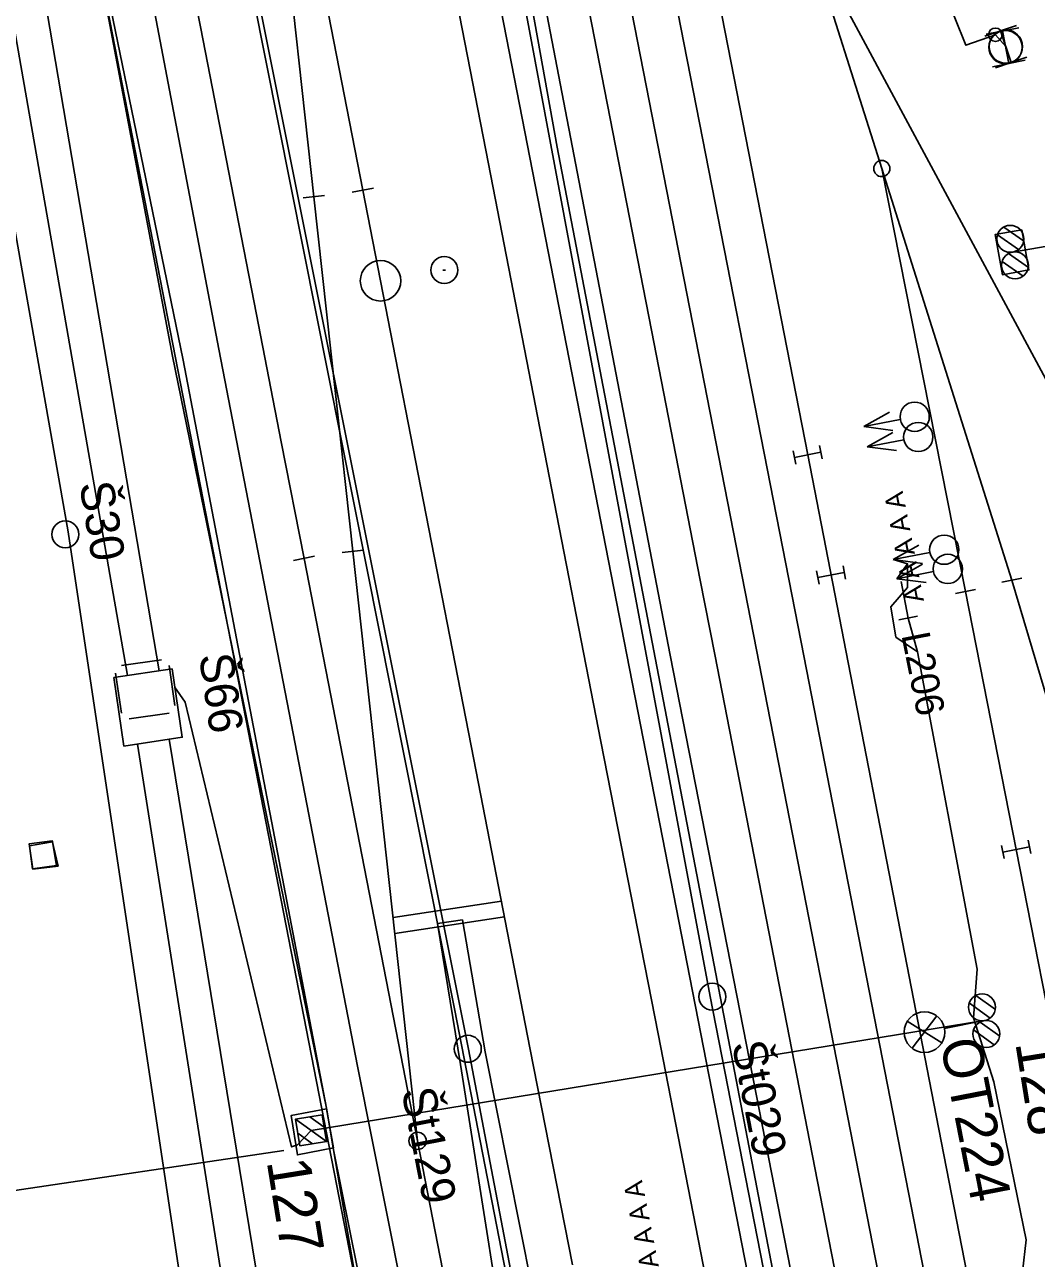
# Model space of a CAD drawing. Extents: x -545846 to -545044, y -1122650 to -1119108.
# Drawn here: x -545638.75 to -545601.28, y -1119708.74 to -1119663.02 of the extents above; entities that cross this region are included whole.
import ezdxf

# ---------------------------------------------------------------- set-up
doc = ezdxf.new("R2010")
doc.units = 0
for name, color, linetype in [('osvětlené plochy-hodnota-obrys', 7, 'Continuous'), ('Vrstva 1', 7, 'Continuous'), ('Vrstva 1 - Koleje', 7, 'Continuous'), ('Vrstva 11 - Trakce', 7, 'Continuous'), ('Vrstva 12', 7, 'Continuous'), ('Vrstva 12 - Trakce zaklady', 7, 'Continuous'), ('Vrstva 19 - Staniceni', 7, 'Continuous'), ('Vrstva 2', 7, 'Continuous'), ('Vrstva 2 - Vyhybky', 7, 'Continuous'), ('Vrstva 25', 7, 'Continuous'), ('Vrstva 26', 7, 'Continuous'), ('Vrstva 27', 7, 'Continuous'), ('Vrstva 28 - zabzar', 7, 'Continuous'), ('Vrstva 3', 7, 'Continuous'), ('Vrstva 3 - Lisy - Pocitaci body', 7, 'Continuous'), ('Vrstva 34', 7, 'Continuous'), ('Vrstva 35', 7, 'Continuous'), ('Vrstva 36', 7, 'Continuous'), ('Vrstva 4 - Teren - stezky - prechody - plochy', 7, 'Continuous'), ('Vrstva 43', 7, 'Continuous'), ('Vrstva 44', 7, 'Continuous'), ('Vrstva 6 - Navesti', 7, 'Continuous'), ('Vrstva 63', 7, 'Continuous'), ('Vrstva 7 - Namezniky-vystroj', 7, 'Continuous')]:
    doc.layers.add(name, color=color, linetype=linetype)

msp = doc.modelspace()

# ---------------------------------------------------------------- linework, layer by layer
at = {"layer": 'osvětlené plochy-hodnota-obrys'}
for points in [[(-545716.386, -1119223.717), (-545705.994, -1119221.66), (-545669.439, -1119408.759), (-545659.4, -1119462.635), (-545647.69, -1119521.347), (-545640.519, -1119558.729), (-545633.585, -1119589.698), (-545629.517, -1119613.814), (-545623.042, -1119645.057), (-545619.034, -1119667.556), (-545607.519, -1119727.517)], [(-545610.895, -1119760.665), (-545622.836, -1119699.488), (-545637.26, -1119626.872), (-545653.542, -1119543.449), (-545716.386, -1119223.717)], [(-545618.794, -1119749.17), (-545664.282, -1119515.639)], [(-545577.736, -1119667.874), (-545599.026, -1119679.685), (-545626.403, -1119628.801)]]:
    msp.add_lwpolyline(points, dxfattribs=at)
at = {"layer": 'Vrstva 1'}
for p, q in [((-545607.007, -1119668.348), (-545603.908, -1119684.024)), ((-545602.189, -1119683.602), (-545597.779, -1119698.482)), ((-545603.908, -1119684.024), (-545602.029, -1119693.583))]:
    msp.add_line(p, q, dxfattribs=at)
for points in [[(-545616.651, -1119643.635), (-545609.752, -1119678.959), (-545604.997, -1119703.439)], [(-545610.067, -1119658.662), (-545609.834, -1119659.409), (-545607.007, -1119668.348), (-545602.189, -1119683.602)], [(-545602.029, -1119693.583), (-545598.565, -1119711.307), (-545594.583, -1119731.822), (-545589.431, -1119758.323), (-545585.705, -1119777.481), (-545581.931, -1119796.878), (-545577.85, -1119817.916), (-545574.229, -1119836.454), (-545566.021, -1119878.608), (-545562.481, -1119896.755), (-545557.82, -1119920.626), (-545554.604, -1119937.13), (-545550.914, -1119956.063), (-545547.745, -1119972.316), (-545544.006, -1119991.525), (-545541.153, -1120006.179), (-545537.243, -1120026.14), (-545533.277, -1120046.572), (-545530.018, -1120063.314), (-545527.775, -1120074.815), (-545524.856, -1120089.755)], [(-545604.997, -1119703.439), (-545603.36, -1119711.808), (-545599.303, -1119732.747), (-545594.117, -1119759.295), (-545590.439, -1119778.194), (-545586.612, -1119797.817), (-545582.864, -1119817.084), (-545578.836, -1119837.699), (-545575.605, -1119854.283), (-545570.113, -1119882.462), (-545567.043, -1119898.144), (-545562.471, -1119921.625), (-545559.225, -1119938.343), (-545555.591, -1119956.995), (-545552.344, -1119973.694), (-545548.708, -1119992.275), (-545545.83, -1120007.048), (-545541.927, -1120027.081), (-545537.977, -1120047.323), (-545534.6, -1120064.642), (-545531.058, -1120082.859), (-545529.535, -1120090.666)]]:
    msp.add_lwpolyline(points, dxfattribs=at)
at = {"layer": 'Vrstva 1 - Koleje'}
for points in [[(-545653.037, -1119506.841), (-545652.888, -1119507.607), (-545652.099, -1119511.657), (-545649.059, -1119527.252), (-545644.851, -1119548.835), (-545643.914, -1119553.655), (-545642.404, -1119561.39), (-545639.909, -1119574.181), (-545637.584, -1119586.095), (-545635.82, -1119595.156), (-545633.965, -1119604.658), (-545632.137, -1119614.029), (-545631.264, -1119618.51), (-545629.612, -1119626.967), (-545629.361, -1119628.256), (-545628.203, -1119634.204), (-545626.651, -1119642.2), (-545624.573, -1119652.836), (-545622.753, -1119662.157), (-545621.579, -1119668.177), (-545619.497, -1119678.862), (-545617.408, -1119689.578), (-545615.292, -1119700.416), (-545613.256, -1119710.876)], [(-545635.682, -1119571.044), (-545635.531, -1119571.819), (-545634.862, -1119575.245), (-545632.499, -1119587.351), (-545629.31, -1119603.689), (-545628.19, -1119609.432), (-545627.412, -1119613.414), (-545625.512, -1119623.176), (-545623.669, -1119632.632), (-545622.964, -1119636.244), (-545621.873, -1119641.833), (-545619.406, -1119654.493), (-545617.375, -1119664.914), (-545615.537, -1119674.339), (-545613.73, -1119683.606), (-545613.194, -1119686.362), (-545611.288, -1119696.135), (-545609.289, -1119706.39), (-545607.258, -1119716.828)], [(-545643.254, -1119606.626), (-545640.837, -1119619.032), (-545638.961, -1119628.669), (-545637.035, -1119638.583), (-545636.36, -1119642.04), (-545635.081, -1119648.585), (-545634.051, -1119653.861), (-545633.095, -1119658.769), (-545632.248, -1119663.101), (-545631.11, -1119668.942), (-545630.167, -1119673.757), (-545629.252, -1119678.474), (-545628.408, -1119682.795), (-545624.202, -1119704.383), (-545620.373, -1119724.031)], [(-545620.224, -1119724.797), (-545620.373, -1119724.031), (-545624.202, -1119704.383), (-545626.602, -1119682.532), (-545627.256, -1119676.573), (-545628.042, -1119669.394), (-545630.443, -1119647.544), (-545633.496, -1119631.903), (-545634.274, -1119627.915), (-545634.427, -1119627.13)], [(-545634.427, -1119627.13), (-545634.274, -1119627.915), (-545630.443, -1119647.544), (-545626.228, -1119669.146), (-545624.179, -1119679.676), (-545622.122, -1119690.247), (-545620.04, -1119700.93), (-545618.466, -1119708.981)]]:
    msp.add_lwpolyline(points, dxfattribs=at)
at = {"layer": 'Vrstva 11 - Trakce'}
for p, q in [((-545580.038, -1119667.607), (-545602.16, -1119671.445)), ((-545602.489, -1119670.516), (-545601.755, -1119671.024)), ((-545602.724, -1119670.808), (-545601.946, -1119671.349)), ((-545602.313, -1119671.502), (-545601.578, -1119672.012)), ((-545602.548, -1119671.797), (-545601.77, -1119672.335)), ((-545603.523, -1119698.991), (-545602.799, -1119699.513)), ((-545603.764, -1119699.279), (-545602.996, -1119699.834)), ((-545628.148, -1119703.993), (-545603.212, -1119699.926)), ((-545603.606, -1119700.27), (-545602.839, -1119700.823)), ((-545603.366, -1119699.98), (-545602.641, -1119700.504)), ((-545628.718, -1119703.578), (-545627.575, -1119704.404)), ((-545628.195, -1119703.494), (-545627.66, -1119703.881)), ((-545628.637, -1119704.099), (-545628.095, -1119704.491))]:
    msp.add_line(p, q, dxfattribs=at)
msp.add_lwpolyline([(-545627.734, -1119703.42), (-545627.575, -1119704.407), (-545628.562, -1119704.566), (-545628.721, -1119703.579)], close=True, dxfattribs=at)
for centre in [(-545602.249, -1119670.953), (-545602.071, -1119671.937), (-545603.292, -1119699.432), (-545603.132, -1119700.42)]:
    msp.add_circle(centre, 0.5, dxfattribs=at)
at = {"layer": 'Vrstva 12'}
for p, q in [((-545638.589, -1119693.376), (-545638.577, -1119693.452)), ((-545637.74, -1119693.263), (-545637.725, -1119693.303)), ((-545638.45, -1119694.309), (-545638.46, -1119694.307)), ((-545637.511, -1119694.2), (-545637.58, -1119694.184))]:
    msp.add_line(p, q, dxfattribs=at)
for points in [[(-545637.511, -1119694.2), (-545638.45, -1119694.309), (-545638.589, -1119693.376), (-545637.74, -1119693.263)], [(-545638.577, -1119693.452), (-545637.725, -1119693.303), (-545637.58, -1119694.184), (-545638.46, -1119694.307)]]:
    msp.add_lwpolyline(points, close=True, dxfattribs=at)
at = {"layer": 'Vrstva 12 - Trakce zaklady'}
for points in [[(-545601.825, -1119670.616), (-545601.556, -1119672.103), (-545602.54, -1119672.281), (-545602.809, -1119670.794), (-545601.825, -1119670.616)], [(-545627.578, -1119703.199), (-545627.313, -1119704.645), (-545628.655, -1119704.904), (-545628.89, -1119703.446), (-545627.578, -1119703.199)]]:
    msp.add_lwpolyline(points, dxfattribs=at)
at = {"layer": 'Vrstva 19 - Staniceni'}
msp.add_circle((-545625.574, -1119672.508), 0.75, dxfattribs=at)
at = {"layer": 'Vrstva 2'}
for p, q in [((-545607.007, -1119668.348), (-545603.908, -1119684.024)), ((-545603.54, -1119683.952), (-545604.276, -1119684.096)), ((-545601.821, -1119683.53), (-545602.557, -1119683.674))]:
    msp.add_line(p, q, dxfattribs=at)
msp.add_lwpolyline([(-545610.067, -1119658.662), (-545609.834, -1119659.409), (-545607.007, -1119668.348), (-545602.189, -1119683.602)], dxfattribs=at)
msp.add_circle((-545607.007, -1119668.348), 0.3, dxfattribs=at)
at = {"layer": 'Vrstva 2 - Vyhybky'}
for p, q in [((-545625.835, -1119669.069), (-545626.621, -1119669.223)), ((-545627.644, -1119669.35), (-545628.44, -1119669.438)), ((-545627, -1119682.576), (-545626.204, -1119682.488)), ((-545628.015, -1119682.718), (-545628.801, -1119682.872))]:
    msp.add_line(p, q, dxfattribs=at)
for points in [[(-545634.427, -1119627.13), (-545634.274, -1119627.915), (-545630.443, -1119647.544), (-545626.228, -1119669.146)], [(-545630.443, -1119647.544), (-545628.042, -1119669.394)], [(-545626.602, -1119682.532), (-545624.202, -1119704.383)], [(-545628.408, -1119682.795), (-545624.202, -1119704.383), (-545620.373, -1119724.031), (-545620.224, -1119724.797)]]:
    msp.add_lwpolyline(points, dxfattribs=at)
msp.add_circle((-545624.202, -1119704.383), 0.32, dxfattribs=at)
at = {"layer": 'Vrstva 25'}
for p, q in [((-545606.063, -1119699.953), (-545604.779, -1119700.745)), ((-545605.884, -1119700.952), (-545604.971, -1119699.753)), ((-545604.684, -1119700.213), (-545603.212, -1119699.926))]:
    msp.add_line(p, q, dxfattribs=at)
msp.add_lwpolyline([(-545628.148, -1119703.993), (-545603.212, -1119699.926)], dxfattribs=at)
msp.add_circle((-545605.425, -1119700.355), 0.754, dxfattribs=at)
at = {"layer": 'Vrstva 26'}
msp.add_lwpolyline([(-545633.203, -1119687.561), (-545632.809, -1119688.12), (-545628.87, -1119704.605), (-545628.65, -1119704.536), (-545628.148, -1119703.993)], dxfattribs=at)
at = {"layer": 'Vrstva 27'}
msp.add_line((-545602.792, -1119663.414), (-545602.808, -1119663.366), dxfattribs=at)
msp.add_circle((-545602.8, -1119663.39), 0.25, dxfattribs=at)
at = {"layer": 'Vrstva 28 - zabzar'}
for points in [[(-545602.41, -1119663.83), (-545602.8, -1119663.39), (-545603.89, -1119663.78), (-545604.71, -1119661.74), (-545605.8, -1119658.61), (-545607.17, -1119655.54), (-545608.43, -1119651.75), (-545609.58, -1119648.66), (-545612.26, -1119642.61), (-545614.17, -1119636.48), (-545616.81, -1119630.32), (-545617.94, -1119624.77), (-545618.68, -1119621.46), (-545618.67, -1119619.01), (-545619.98, -1119615.4), (-545621.7, -1119610.72), (-545623.18, -1119606.89), (-545623.86, -1119604.94), (-545624.45, -1119605.24)], [(-545605.69, -1119686.26), (-545606.49, -1119685.71), (-545606.67, -1119684.59), (-545606.05, -1119683.87), (-545606.05, -1119683)], [(-545606.58, -1119682.84), (-545606.05, -1119683), (-545606.45, -1119683.55)], [(-545596.02, -1119736.86), (-545597.69, -1119727.72), (-545598.81, -1119721.77), (-545601.22, -1119710.53), (-545601.8, -1119709.24), (-545601.66, -1119708.05), (-545602.86, -1119702.19), (-545603.61, -1119699.82), (-545603.48, -1119698.02), (-545605.69, -1119686.26), (-545606.03, -1119685.01)]]:
    msp.add_lwpolyline(points, dxfattribs=at)
at = {"layer": 'Vrstva 3'}
for p, q in [((-545601.936, -1119663.128), (-545603.145, -1119663.365)), ((-545602.54, -1119663.246), (-545602.304, -1119664.456)), ((-545601.699, -1119664.337), (-545602.908, -1119664.574)), ((-545607.677, -1119677.912), (-545606.727, -1119677.376)), ((-545607.677, -1119677.912), (-545606.322, -1119677.649)), ((-545607.677, -1119677.912), (-545606.595, -1119678.053)), ((-545607.543, -1119678.662), (-545606.593, -1119678.126)), ((-545607.543, -1119678.662), (-545606.188, -1119678.399)), ((-545610.291, -1119678.81), (-545610.195, -1119679.3)), ((-545609.261, -1119678.863), (-545610.243, -1119679.055)), ((-545609.309, -1119678.618), (-545609.213, -1119679.108)), ((-545607.543, -1119678.662), (-545606.461, -1119678.803)), ((-545602.472, -1119693.924), (-545602.568, -1119693.433)), ((-545602.52, -1119693.679), (-545601.538, -1119693.487)), ((-545601.49, -1119693.733), (-545601.586, -1119693.242))]:
    msp.add_line(p, q, dxfattribs=at)
for centre, radius in [((-545602.421, -1119663.853), 0.616), ((-545605.789, -1119677.547), 0.542), ((-545605.655, -1119678.297), 0.542)]:
    msp.add_circle(centre, radius, dxfattribs=at)
at = {"layer": 'Vrstva 3 - Lisy - Pocitaci body'}
for p, q in [((-545603.19, -1119663.441), (-545602.021, -1119663.05)), ((-545602.215, -1119664.414), (-545602.605, -1119663.246)), ((-545602.799, -1119664.61), (-545601.63, -1119664.219)), ((-545606.58, -1119682.84), (-545605.63, -1119682.303)), ((-545606.58, -1119682.84), (-545605.226, -1119682.575)), ((-545606.58, -1119682.84), (-545605.498, -1119682.98)), ((-545606.45, -1119683.55), (-545605.5, -1119683.014)), ((-545609.426, -1119683.261), (-545609.33, -1119683.752)), ((-545608.396, -1119683.315), (-545609.378, -1119683.507)), ((-545608.444, -1119683.07), (-545608.348, -1119683.561)), ((-545606.45, -1119683.55), (-545605.095, -1119683.287)), ((-545606.45, -1119683.55), (-545605.368, -1119683.691))]:
    msp.add_line(p, q, dxfattribs=at)
for centre, radius in [((-545602.411, -1119663.828), 0.616), ((-545604.693, -1119682.473), 0.542), ((-545604.562, -1119683.185), 0.542)]:
    msp.add_circle(centre, radius, dxfattribs=at)
at = {"layer": 'Vrstva 34'}
for p, q in [((-545635.173, -1119686.763), (-545633.688, -1119686.551)), ((-545635.173, -1119688.531), (-545635.385, -1119687.046)), ((-545633.405, -1119686.763), (-545633.193, -1119688.248)), ((-545633.405, -1119688.531), (-545634.89, -1119688.743))]:
    msp.add_line(p, q, dxfattribs=at)
at = {"layer": 'Vrstva 35'}
for p, q in [((-545634.944, -1119687.133), (-545642.159, -1119645.823)), ((-545633.773, -1119686.964), (-545640.811, -1119645.587)), ((-545628.775, -1119726.428), (-545634.574, -1119689.677)), ((-545627.388, -1119726.198), (-545633.404, -1119689.501))]:
    msp.add_line(p, q, dxfattribs=at)
at = {"layer": 'Vrstva 36'}
for p, q in [((-545633.292, -1119686.892), (-545633.292, -1119686.892)), ((-545635.449, -1119687.205), (-545635.449, -1119687.205)), ((-545632.921, -1119689.426), (-545632.921, -1119689.426)), ((-545635.076, -1119689.752), (-545635.076, -1119689.752))]:
    msp.add_line(p, q, dxfattribs=at)
msp.add_lwpolyline([(-545635.449, -1119687.205), (-545633.292, -1119686.892), (-545632.921, -1119689.426), (-545635.076, -1119689.752)], close=True, dxfattribs=at)
msp.add_lwpolyline([(-545635.449, -1119687.205), (-545633.292, -1119686.892), (-545632.921, -1119689.426), (-545635.076, -1119689.752), (-545635.449, -1119687.205)], dxfattribs=at)
at = {"layer": 'Vrstva 4 - Teren - stezky - prechody - plochy'}
for points in [[(-545668.116, -1119499.514), (-545669.067, -1119499.733), (-545667.149, -1119508.296), (-545664.169, -1119519.775), (-545660.463, -1119535.199), (-545657.369, -1119550.681), (-545650.63, -1119584.9), (-545650.137, -1119587.57), (-545643.597, -1119621.824), (-545639.676, -1119641.733), (-545638.648, -1119646.558), (-545637.372, -1119653.536), (-545637.393, -1119653.539), (-545632.884, -1119675.451), (-545627.579, -1119703.177), (-545627.31, -1119704.719), (-545625.835, -1119712.063)], [(-545668.116, -1119499.514), (-545665.721, -1119507.929), (-545662.615, -1119519.622), (-545659.148, -1119534.332), (-545655.765, -1119550.675), (-545641.939, -1119621.169), (-545637.993, -1119641.248), (-545631.568, -1119675.037), (-545626.43, -1119701.616), (-545620.933, -1119729.23), (-545619.776, -1119736.256), (-545618.414, -1119746.042), (-545618.118, -1119750.155), (-545617.307, -1119763.323), (-545616.619, -1119772.592), (-545616.223, -1119779.957), (-545616.135, -1119786.617)], [(-545624.215, -1119622.224), (-545623.342, -1119622.007), (-545620.608, -1119632.171), (-545618.464, -1119642.593), (-545609.99, -1119685.9), (-545599.422, -1119740.168), (-545590.883, -1119784.038), (-545582.301, -1119828.162), (-545571.506, -1119883.387), (-545561.049, -1119937.185), (-545548.968, -1119999.368), (-545536.73, -1120062.107), (-545526.255, -1120115.744), (-545515.983, -1120168.544), (-545503.995, -1120229.495), (-545494.446, -1120278.921), (-545489.088, -1120306.388), (-545486.967, -1120316.535), (-545487.846, -1120316.754)], [(-545624.215, -1119622.224), (-545621.684, -1119634.807), (-545620.048, -1119643.216), (-545611.648, -1119686.181), (-545601.152, -1119739.942), (-545592.571, -1119783.992), (-545583.867, -1119828.341), (-545573.059, -1119883.823), (-545562.652, -1119937.218), (-545550.46, -1119999.458), (-545538.284, -1120062.171), (-545527.796, -1120116.054), (-545517.608, -1120168.62), (-545505.551, -1120230.109), (-545495.948, -1120279.349), (-545494.121, -1120288.848), (-545492.075, -1120298.544), (-545490.237, -1120306.578), (-545487.846, -1120316.754)], [(-545627.289, -1119622.488), (-545623.041, -1119643.798), (-545614.848, -1119686.378), (-545604.257, -1119740.381), (-545596.077, -1119782.585), (-545587.168, -1119828.353), (-545576.202, -1119884.317), (-545565.971, -1119936.976), (-545553.74, -1119999.834), (-545541.535, -1120062.236), (-545531.079, -1120116.013), (-545520.819, -1120168.515), (-545508.831, -1120230.344), (-545499.12, -1120279.845), (-545497.248, -1120289.164), (-545495.162, -1120299.078), (-545493.408, -1120306.853), (-545489.261, -1120323.659), (-545486.768, -1120332.638), (-545482.019, -1120349.033), (-545479.258, -1120359.037), (-545477.044, -1120368.814), (-545475.362, -1120376.928)], [(-545628.853, -1119622.763), (-545624.686, -1119644.063), (-545616.354, -1119686.873), (-545605.869, -1119740.58), (-545597.619, -1119782.547), (-545588.666, -1119828.365), (-545577.778, -1119884.555), (-545567.555, -1119936.921), (-545555.278, -1120000.024), (-545543.118, -1120062.357), (-545532.633, -1120116.151), (-545522.436, -1120168.075), (-545510.345, -1120230.332), (-545500.633, -1120280.001), (-545495.304, -1120307.199), (-545490.342, -1120331.504), (-545485.9, -1120353.688), (-545480.839, -1120378)], [(-545637.393, -1119653.539), (-545633.274, -1119675.3), (-545627.579, -1119703.177), (-545627.31, -1119704.719), (-545626.06, -1119712.07), (-545622.496, -1119729.428)], [(-545627.579, -1119703.177), (-545632.884, -1119675.451), (-545637.393, -1119653.539)], [(-545488.754, -1120379.549), (-545491.925, -1120363.788), (-545496.278, -1120342.782), (-545500.506, -1120321.731), (-545508.599, -1120280.828), (-545518.82, -1120228.621), (-545531.029, -1120165.923), (-545540.626, -1120116.248), (-545552.245, -1120057.042), (-545557.488, -1120030.03), (-545563.439, -1119999.512), (-545572.128, -1119954.79), (-545581.61, -1119906.246), (-545591.458, -1119855.639), (-545600.962, -1119806.943), (-545610.434, -1119758.233), (-545616.648, -1119726.461), (-545621.696, -1119701.088), (-545622.533, -1119696.196), (-545623.462, -1119696.331)], [(-545490.916, -1120379.972), (-545493.99, -1120364.147), (-545502.163, -1120322.09), (-545510.164, -1120281.035), (-545520.235, -1120229.023), (-545532.517, -1120166.017), (-545542.296, -1120116.028), (-545553.809, -1120057.082), (-545558.932, -1120030.597), (-545564.969, -1119999.794), (-545573.753, -1119955.036), (-545583.127, -1119906.578), (-545593.017, -1119855.856), (-545602.553, -1119806.891), (-545612.123, -1119758.671), (-545618.333, -1119726.047), (-545620.676, -1119713.873), (-545622.612, -1119701.558), (-545623.462, -1119696.331)], [(-545622.496, -1119729.428), (-545625.835, -1119712.063), (-545627.31, -1119704.719)]]:
    msp.add_lwpolyline(points, dxfattribs=at)
at = {"layer": 'Vrstva 43'}
for centre in [(-545637.247, -1119681.906), (-545613.286, -1119699.04), (-545622.342, -1119700.971)]:
    msp.add_circle(centre, 0.5, dxfattribs=at)
at = {"layer": 'Vrstva 44'}
for points in [[(-545654.9, -1119582.222), (-545645.965, -1119631.818), (-545637.145, -1119681.816), (-545629.836, -1119730.566), (-545626.416, -1119761.521), (-545622.849, -1119813.009), (-545619.592, -1119863.304), (-545618.858, -1119914.175), (-545618.881, -1119950.565), (-545618.715, -1119963.415), (-545629.02, -1119997.179)], [(-545622.746, -1119648.835), (-545613.361, -1119699.038), (-545602.122, -1119756.581), (-545611.004, -1119758.624), (-545611.36, -1119758.757)], [(-545632.322, -1119650.948), (-545622.321, -1119700.988), (-545611.338, -1119758.596), (-545611.36, -1119758.757), (-545611.449, -1119758.784)]]:
    msp.add_lwpolyline(points, dxfattribs=at)
at = {"layer": 'Vrstva 6 - Navesti'}
for p, q in [((-545606.294, -1119683.649), (-545606.03, -1119685.01)), ((-545606.374, -1119685.077), (-545605.686, -1119684.943))]:
    msp.add_line(p, q, dxfattribs=at)
at = {"layer": 'Vrstva 63'}
msp.add_line((-545629.158, -1119704.744), (-545685.803, -1119713.163), dxfattribs=at)
at = {"layer": 'Vrstva 7 - Namezniky-vystroj'}
for p, q in [((-545623.263, -1119672.11), (-545623.163, -1119672.11)), ((-545625.111, -1119696.104), (-545621.099, -1119695.494)), ((-545625.046, -1119696.701), (-545620.985, -1119696.083))]:
    msp.add_line(p, q, dxfattribs=at)
msp.add_circle((-545623.213, -1119672.11), 0.5, dxfattribs=at)

# ---------------------------------------------------------------- texts
at = {"layer": 'Vrstva 11 - Trakce'}
for s, p in [('128', (-545602.066, -1119700.754)), ('127', (-545629.795, -1119705.141))]:
    msp.add_text(s, height=1.6, rotation=279.1562, dxfattribs=at).set_placement(p)
at = {"layer": 'Vrstva 25'}
msp.add_text('OT224', height=1.5, rotation=281.0303, dxfattribs=at).set_placement((-545604.851, -1119700.713))
at = {"layer": 'Vrstva 34'}
msp.add_text('Š66', height=1.25, rotation=278.1347, dxfattribs=at).set_placement((-545632.301, -1119686.393))
at = {"layer": 'Vrstva 43'}
for s, rotation, p in [('Š30', 279.317, (-545636.733, -1119680.035)), ('Št029', 280.9998, (-545612.566, -1119700.781)), ('Št129', 280.9998, (-545624.802, -1119702.515))]:
    msp.add_text(s, height=1.25, rotation=rotation, dxfattribs=at).set_placement(p)
at = {"layer": 'Vrstva 6 - Navesti'}
for s, height, rotation, p in [('  A A A A A ', 0.7, 100.9923, (-545605.343, -1119684.877)), ('L206', 1.05, 281.1588, (-545606.284, -1119685.634)), ('  CA A A A A A ', 0.7, 101.0739, (-545614.693, -1119711.946))]:
    msp.add_text(s, height=height, rotation=rotation, dxfattribs=at).set_placement(p)

doc.saveas('drawing.dxf')
